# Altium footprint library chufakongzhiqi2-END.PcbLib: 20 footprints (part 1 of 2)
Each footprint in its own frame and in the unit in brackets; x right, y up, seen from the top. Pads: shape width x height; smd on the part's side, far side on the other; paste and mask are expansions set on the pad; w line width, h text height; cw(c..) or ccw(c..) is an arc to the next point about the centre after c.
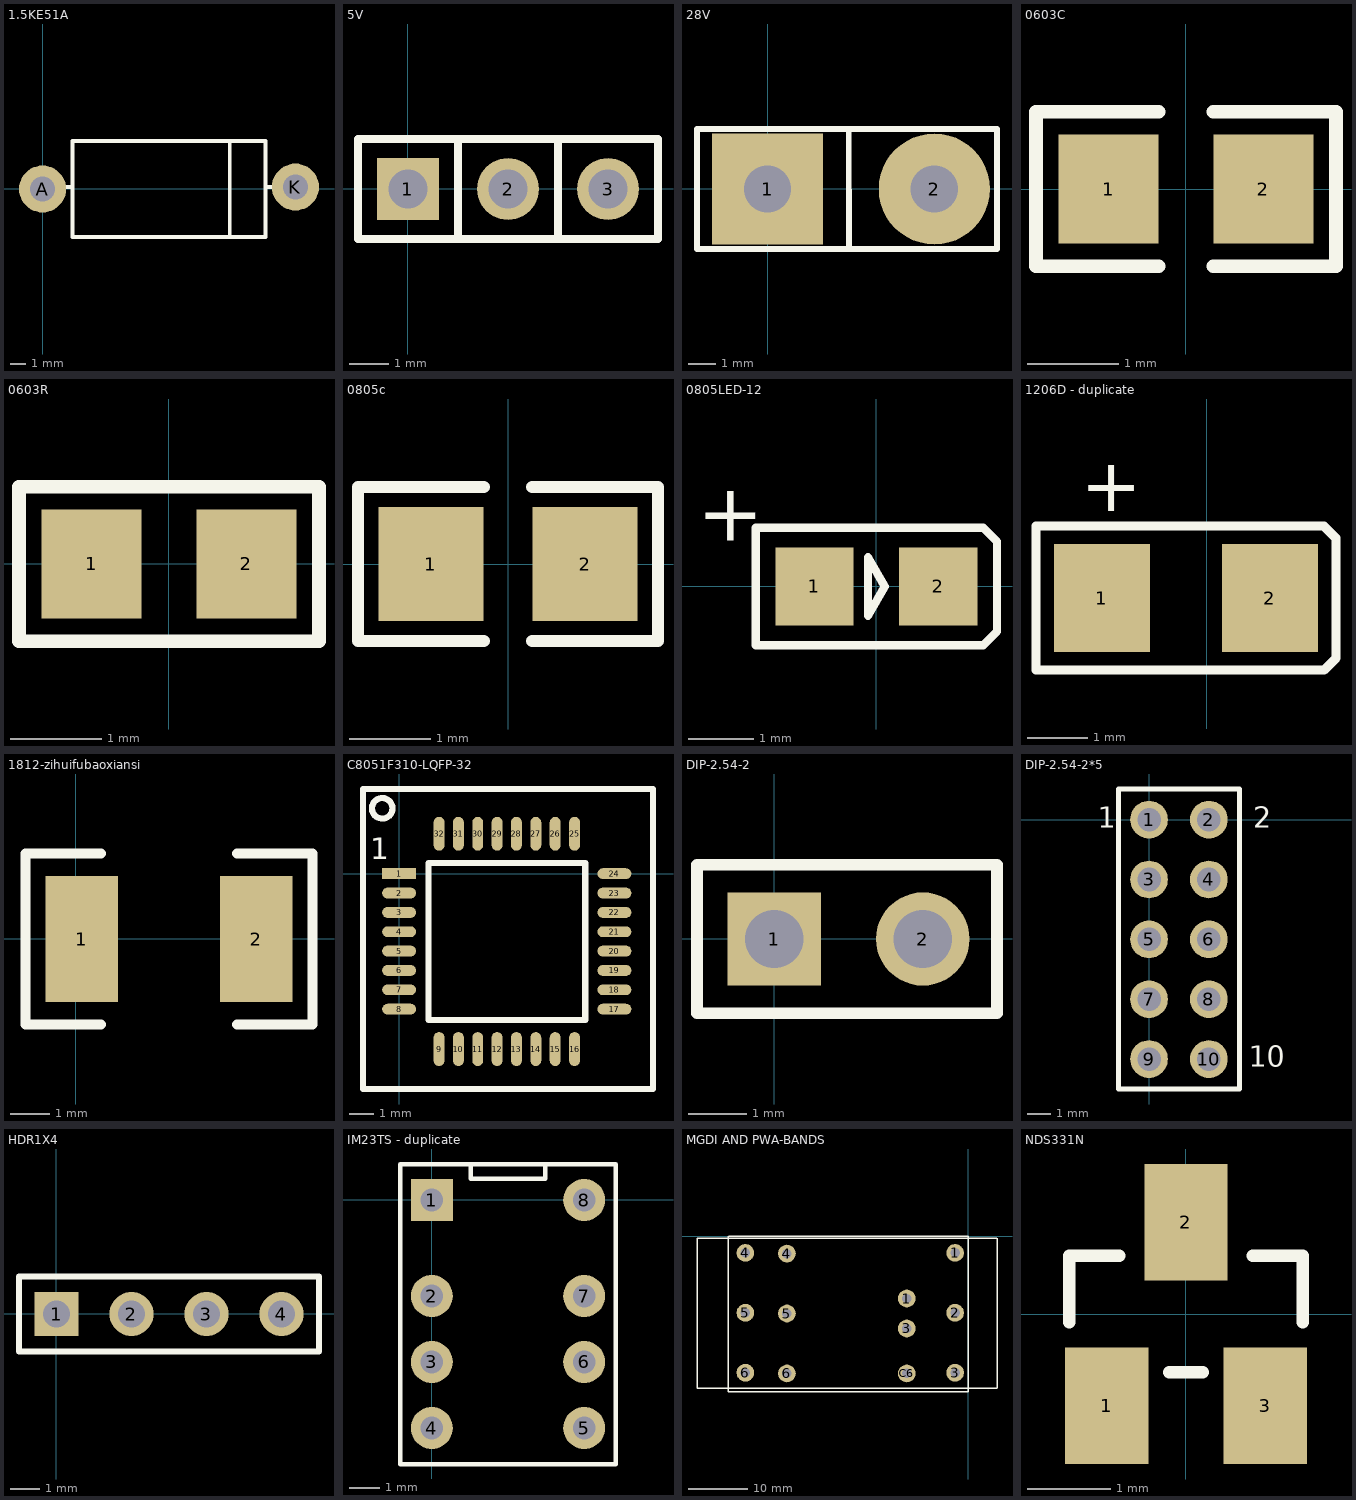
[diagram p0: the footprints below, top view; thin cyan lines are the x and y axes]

## 1.5KE51A [mm] "1.02mm*5.2mm*10mm(16.5mm)"
pads (2):
  round 3 hole 1.6: A(0,0) K(16.129,0.127)
Top Overlay:
  lines w0.254: 1.397,0.127 1.905,0.127 ; 11.811,-3.048 14.224,-3.048 14.224,3.048 11.938,3.048 ; 14.224,0.127 14.732,0.127 ; 11.938,3.048 11.938,-3.048 1.905,-3.048 1.905,3.048 11.938,3.048

## 5V [mil]
height 68.9
pads (3):
  rect 62x62 hole 39.37: 1(0.19,-0.28)
  round 62 hole 39.37: 2(100.19,-0.28) 3(200.19,-0.28)
Top Overlay:
  lines w8: 50.19,-50.28 50.19,49.72 ; 50.19,-50.28 250.19,-50.28 250.19,49.72 50.19,49.72 ; 50.19,-50.28 50.19,49.72 ; 150.19,-50.28 -49.81,-50.28 -49.81,49.72 150.19,49.72 ; 150.19,-50.28 150.19,49.72 ; 150.19,-50.28 150.19,49.72

## 28V [mm]
height 1.75
pads (2):
  rect 4x4 hole 1.7: 1(0,0)
  round 4 hole 1.7: 2(6,0)
Top Overlay:
  lines w0.203: 2.921,2.159 2.927,-2.159 ; -2.54,-2.159 -2.54,2.159 8.255,2.159 8.255,-2.159 -2.54,-2.159

## 0603C [mm]
height 11
pads (2):
  rect 1.1x1.2 smd: 1(-0.85,0) 2(0.85,0)
Top Overlay:
  lines w0.15: -0.3,-0.85 -1.65,-0.85 -1.65,0.85 -0.3,0.85 ; 0.3,-0.85 1.65,-0.85 1.65,0.85 0.3,0.85

## 0603R [mm]
height 11
pads (2):
  rect 1.1x1.2 smd: 1(-0.85,0) 2(0.85,0)
Top Overlay:
  lines w0.15: -1.65,-0.85 -1.65,0.85 1.65,0.85 1.65,-0.85 -1.65,-0.85

## 0805c [mm]
pads (2):
  rect 1.3x1.4 smd: 1(-0.95,0) 2(0.95,0)
Top Overlay:
  lines w0.15: -1.85,-0.95 -1.85,0.95 ; 1.85,-0.95 1.85,0.95
  lines w0.152: -1.85,-0.95 -0.3,-0.95 ; -1.85,0.95 -0.3,0.95 ; 0.3,-0.95 1.85,-0.95 ; 0.3,0.95 1.85,0.95

## 0805LED-12 [mm]
height 11
pads (2):
  rect 1.2x1.2 smd: 1(-0.95,0) 2(0.95,0)
Top Overlay:
  lines w0.127: -1.85,-0.9 1.64,-0.9 1.85,-0.69 1.85,0.69 1.64,0.9 -1.85,0.9 -1.85,-0.9 ; -0.127,-0.45 -0.127,0.45 0.127,0 -0.127,-0.45
  text "+" at -2.75,0.7 h0.89

## 1206D - duplicate [mm]
pads (2):
  rect 1.6x1.8 smd: 1(-1.75,3.3) 2(1.05,3.3)
Top Overlay:
  lines w0.15: -2.85,2.1 -2.85,4.5 1.95,4.5 2.15,4.3 2.15,4.25 2.15,2.3 1.95,2.1 -2.85,2.1
  text "+" at -2.1,4.75 h0.89

## 1812-zihuifubaoxiansi [mil] "1.1A BAOXIAN"
height 68.9
pads (2):
  rect 72x125 smd: 1(6,0) 2(179,0)
Top Overlay:
  lines w10: 25,-85 -50,-85 -50,85 25,85 ; 160,-85 235,-85 235,85 160,85

## C8051F310-LQFP-32 [mm]
pads (32):
  rect 1.4x0.45 smd: 1(0,0)
  oval 1.4x0.45 smd: 2(0,-0.8) 3(0,-1.6) 4(0,-2.4) 5(0,-3.2) 6(0,-4) 7(0,-4.8) 8(0,-5.6) 17(8.9,-5.6) 18(8.9,-4.8) 19(8.9,-4) 20(8.9,-3.2) 21(8.9,-2.4) 22(8.9,-1.6) 23(8.9,-0.8) 24(8.9,0)
  oval 0.45x1.4 smd: 9(1.65,-7.25) 10(2.45,-7.25) 11(3.25,-7.25) 12(4.05,-7.25) 13(4.85,-7.25) 14(5.65,-7.25) 15(6.45,-7.25) 16(7.25,-7.25) 25(7.25,1.65) 26(6.45,1.65) 27(5.65,1.65) 28(4.85,1.65) 29(4.05,1.65) 30(3.25,1.65) 31(2.45,1.65) 32(1.65,1.65)
Top Overlay:
  circle w0.254: c-0.7,2.7 r0.424
  lines w0.254: -1.5,-8.9 10.5,-8.9 10.5,3.5 -1.5,3.5 -1.5,-8.9 ; 1.208,-6.042 1.208,0.442 7.692,0.442 7.692,-6.042 1.208,-6.042
  text "1" at -1.2,0.6 h0.89

## DIP-2.54-2 [mm]
pads (2):
  rect 1.6x1.6 hole 1: 1(0,0)
  round 1.6 hole 1: 2(2.54,0)
Top Overlay:
  lines w0.203: -1.325,-1.27 -1.325,1.27 3.81,1.27 3.81,-1.27 -1.325,-1.27

## DIP-2.54-2*5 [mm]
pads (10):
  round 1.6 hole 1: 1(0,0) 2(2.54,0) 3(0,-2.54) 4(2.54,-2.54) 5(0,-5.08) 6(2.54,-5.08) 7(0,-7.62) 8(2.54,-7.62) 9(0,-10.16) 10(2.54,-10.16)
Top Overlay:
  lines w0.203: -1.3,-11.43 -1.3,1.3 3.84,1.3 3.84,-11.4 3.84,-11.43 -1.3,-11.43
  text "1" at -2.178,-0.344 h0.89
  text "2" at 4.426,-0.344 h0.89
  text "10" at 4.23,-10.486 h0.89

## HDR1X4 [mm] "Connector; Header; 4 Position"
pads (4):
  rect 1.5x1.5 hole 0.9: 1(0,0)
  round 1.5 hole 0.9: 2(2.54,0) 3(5.08,0) 4(7.62,0)
Top Overlay:
  lines w0.2: -1.27,-1.27 8.89,-1.27 8.89,1.27 -1.27,1.27 -1.27,-1.27

## IM23TS - duplicate [mm]
pads (8):
  rect 1.4x1.4 hole 0.75: 1(0,0)
  round 1.4 hole 0.75: 2(0,-3.2) 3(0,-5.4) 4(0,-7.6) 5(5.08,-7.6) 6(5.08,-5.4) 7(5.08,-3.2) 8(5.08,0)
Top Overlay:
  lines w0.15: 1.29,1.2 1.29,0.7 3.79,0.7 3.79,1.2 ; -1.06,-8.8 -1.06,1.2 6.14,1.2 6.14,-8.8 -1.06,-8.8

## MGDI AND PWA-BANDS [mm] "LIANGZHONGJIANRONG"
pads (12):
  round 3 hole 1.6: 1(-10.414,-10.585) 1(-2.22,-2.84) 2(-2.22,-13) 3(-10.414,-15.665) 3(-2.22,-23.16) 4(-37.78,-2.84) 4(-30.734,-2.965) 5(-37.78,-13) 5(-30.734,-13.125) 6(-37.78,-23.16) 6(-30.734,-23.285) C6(-10.414,-23.285)
Top Overlay:
  lines w0.254: -45.974,-25.781 4.826,-25.781 ; -45.974,-25.756 -45.974,-0.356 ; -45.974,-0.381 4.826,-0.381 ; -40.64,0 -40.64,-26.416 0,-26.416 0,0 ; -40.615,-0.025 0.025,-0.025 ; 4.877,-25.756 4.877,-0.356

## NDS331N [mm]
pads (3):
  rect 1x1.4 smd: 1(-0.95,-1.1) 2(0,1.1) 3(0.95,-1.1)
Top Overlay:
  lines w0.15: -1.4,-0.1 -1.4,0.7 -0.8,0.7 ; -0.2,-0.7 0.2,-0.7 ; 0.8,0.7 1.4,0.7 1.4,-0.1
